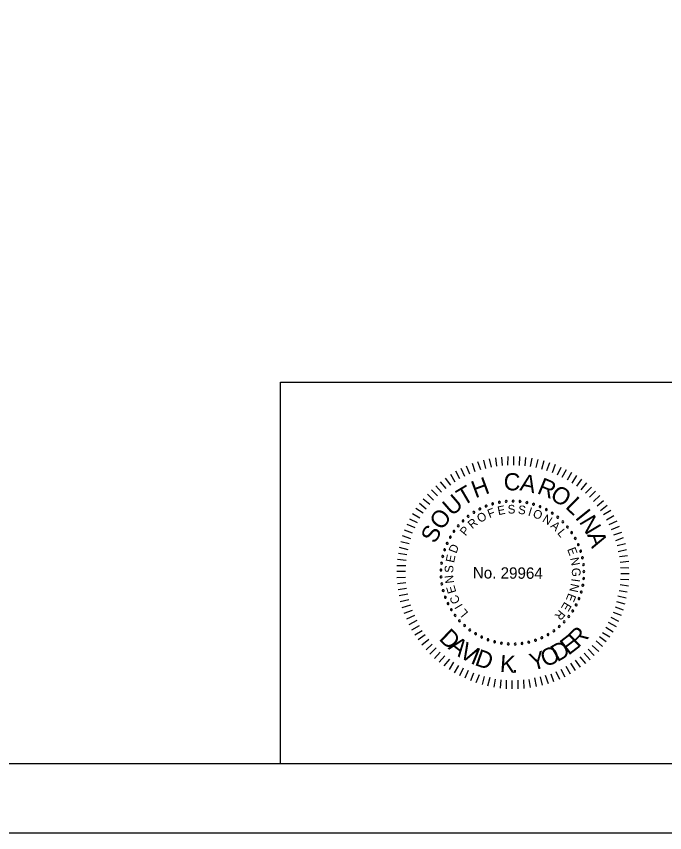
# Model space of a CAD drawing. Extents: x -133.1 to -97, y -1.7 to 20.3.
# Drawn here: x -112.41 to -107.74, y -1.69 to 4.2 of the extents above; entities that cross this region are included whole.
import ezdxf

# ---------------------------------------------------------------- set-up
doc = ezdxf.new("R2010")
doc.units = 0
for name, color, linetype in [('BR_BORDER LINES', 7, 'Continuous'), ('BR_TEXT', 7, 'Continuous'), ('Level 31', 7, 'Continuous')]:
    doc.layers.add(name, color=color, linetype=linetype)

msp = doc.modelspace()

# ---------------------------------------------------------------- linework, layer by layer
at = {"layer": 'BR_BORDER LINES'}
for p, q in [((-110.5071, 1.5591), (-105.1419, 1.5591)), ((-110.5071, -1.191), (-110.5071, 1.5591)), ((-131.3076, -1.191), (-97.6416, -1.191))]:
    msp.add_line(p, q, dxfattribs=at)
at = {"layer": 'BR_TEXT'}
for p, q in [((-108.9849, 0.9447), (-108.999, 1.0041)), ((-108.9454, 0.9521), (-108.9543, 1.0131)), ((-108.9059, 0.9561), (-108.9097, 1.017)), ((-108.8664, 0.9584), (-108.8658, 1.0227)), ((-108.8243, 0.9606), (-108.8238, 1.0224)), ((-108.7823, 0.9577), (-108.78, 1.022)), ((-108.742, 0.9548), (-108.7372, 1.0156)), ((-108.7034, 0.9501), (-108.6926, 1.011)), ((-108.6631, 0.9421), (-108.6489, 1.0012)), ((-109.1406, 0.8954), (-109.1642, 0.9514)), ((-109.1019, 0.9122), (-109.1229, 0.9708)), ((-109.0623, 0.9248), (-109.0842, 0.9824)), ((-109.0262, 0.9348), (-109.0394, 0.9958)), ((-108.622, 0.9314), (-108.606, 0.9922)), ((-108.5852, 0.9208), (-108.5633, 0.9781)), ((-108.5458, 0.9076), (-108.5239, 0.9658)), ((-108.5099, 0.8902), (-108.482, 0.9457)), ((-109.2475, 0.8371), (-109.278, 0.8914)), ((-109.2122, 0.8608), (-109.2426, 0.9151)), ((-109.1777, 0.8785), (-109.2039, 0.9345)), ((-108.474, 0.8727), (-108.4427, 0.9282)), ((-108.4364, 0.8544), (-108.4042, 0.9082)), ((-108.4031, 0.8301), (-108.3692, 0.8839)), ((-109.3123, 0.7904), (-109.3522, 0.8405)), ((-109.2786, 0.8159), (-109.3177, 0.8668)), ((-108.3699, 0.8083), (-108.3334, 0.8587)), ((-108.3375, 0.7824), (-108.2968, 0.8318)), ((-109.3745, 0.7386), (-109.4188, 0.7827)), ((-109.3451, 0.7658), (-109.3868, 0.8107)), ((-108.3059, 0.7572), (-108.2627, 0.8014)), ((-108.2779, 0.7295), (-108.2346, 0.7729)), ((-109.4291, 0.6763), (-109.4786, 0.7154)), ((-109.4039, 0.7079), (-109.4474, 0.7503)), ((-108.2498, 0.6984), (-108.2022, 0.74)), ((-109.4551, 0.6431), (-109.5046, 0.683)), ((-108.2226, 0.6664), (-108.1759, 0.7046)), ((-108.1988, 0.6327), (-108.1496, 0.6718)), ((-109.5012, 0.5774), (-109.5549, 0.6096)), ((-109.4768, 0.6141), (-109.5306, 0.6472)), ((-108.1768, 0.6034), (-108.1242, 0.6355)), ((-108.1548, 0.5663), (-108.1013, 0.5976)), ((-109.5361, 0.5065), (-109.5933, 0.5318)), ((-109.5186, 0.5432), (-109.575, 0.5711)), ((-108.137, 0.5318), (-108.0793, 0.5588)), ((-109.5536, 0.468), (-109.6117, 0.4899)), ((-108.1193, 0.4948), (-108.0624, 0.5192)), ((-108.1025, 0.456), (-108.0456, 0.477)), ((-109.5659, 0.4278), (-109.6275, 0.4506)), ((-108.0891, 0.4156), (-108.0314, 0.4374)), ((-109.5854, 0.3498), (-109.6479, 0.3658)), ((-109.5782, 0.3918), (-109.639, 0.4069)), ((-108.079, 0.3794), (-108.0189, 0.3935)), ((-109.596, 0.3138), (-109.6569, 0.3221)), ((-108.0708, 0.3373), (-108.0106, 0.3522)), ((-108.0625, 0.3012), (-108.0033, 0.3084)), ((-109.6006, 0.2727), (-109.6624, 0.2801)), ((-108.056, 0.26), (-107.995, 0.2663)), ((-109.6056, 0.1921), (-109.6682, 0.1926)), ((-109.6035, 0.2333), (-109.6679, 0.2338)), ((-108.0546, 0.2205), (-107.9945, 0.22)), ((-108.0524, 0.1793), (-107.9915, 0.1788)), ((-109.6042, 0.1492), (-109.6686, 0.148)), ((-108.0553, 0.1364), (-107.9952, 0.1342)), ((-109.602, 0.1105), (-109.6638, 0.1033)), ((-109.598, 0.0693), (-109.659, 0.0604)), ((-108.0574, 0.0978), (-107.9965, 0.0896)), ((-109.5881, 0.0297), (-109.6508, 0.0165)), ((-108.0735, 0.0172), (-108.0135, 0.003)), ((-108.0645, 0.0566), (-108.0054, 0.0467)), ((-109.5815, -0.0124), (-109.6426, -0.0265)), ((-109.5698, -0.0493), (-109.6318, -0.0703)), ((-108.0824, -0.0248), (-108.0224, -0.0398)), ((-109.5582, -0.0881), (-109.6167, -0.1091)), ((-108.107, -0.1001), (-108.0506, -0.122)), ((-108.093, -0.0615), (-108.0357, -0.0835)), ((-109.5413, -0.1251), (-109.599, -0.1521)), ((-109.5244, -0.1613), (-109.5813, -0.1909)), ((-108.1428, -0.1727), (-108.0856, -0.2032)), ((-108.1245, -0.1368), (-108.0681, -0.1647)), ((-109.5076, -0.1984), (-109.5619, -0.2297)), ((-109.4838, -0.2355), (-109.5382, -0.2668)), ((-108.1612, -0.2095), (-108.1082, -0.2417)), ((-109.4626, -0.2648), (-109.5127, -0.3013)), ((-108.2063, -0.2752), (-108.1577, -0.3125)), ((-108.1838, -0.2462), (-108.1317, -0.2784)), ((-109.4372, -0.2985), (-109.4873, -0.3376)), ((-109.4125, -0.3321), (-109.4567, -0.373)), ((-108.2583, -0.3417), (-108.2115, -0.3833)), ((-108.2306, -0.3084), (-108.1846, -0.3483)), ((-109.3836, -0.3582), (-109.4286, -0.4032)), ((-109.3547, -0.3884), (-109.3971, -0.4344)), ((-108.3155, -0.397), (-108.273, -0.4437)), ((-108.2869, -0.3672), (-108.2444, -0.413)), ((-109.3222, -0.4144), (-109.363, -0.4613)), ((-109.289, -0.4404), (-109.3289, -0.4882)), ((-109.2583, -0.4622), (-109.2896, -0.5142)), ((-108.4139, -0.4691), (-108.3808, -0.5217)), ((-108.3802, -0.448), (-108.3446, -0.4963)), ((-108.3474, -0.4225), (-108.3075, -0.47)), ((-109.2233, -0.4847), (-109.2546, -0.5386)), ((-109.1891, -0.5048), (-109.2162, -0.5603)), ((-109.1523, -0.5222), (-109.1769, -0.5778)), ((-108.5216, -0.5274), (-108.4947, -0.5835)), ((-108.4855, -0.5106), (-108.455, -0.5666)), ((-108.4475, -0.4911), (-108.4162, -0.5455)), ((-109.1139, -0.5397), (-109.1358, -0.5962)), ((-109.0745, -0.552), (-109.0973, -0.6102)), ((-109.0386, -0.5644), (-109.0528, -0.6235)), ((-108.9974, -0.5716), (-109.0126, -0.6333)), ((-108.9581, -0.5831), (-108.968, -0.6413)), ((-108.9186, -0.5877), (-108.9234, -0.6494)), ((-108.7161, -0.5851), (-108.7062, -0.6435)), ((-108.6756, -0.5742), (-108.6624, -0.6361)), ((-108.6344, -0.5677), (-108.6194, -0.627)), ((-108.5974, -0.556), (-108.5764, -0.6145)), ((-108.5578, -0.5443), (-108.5368, -0.6011)), ((-108.8792, -0.5906), (-108.8797, -0.6524)), ((-108.8372, -0.5935), (-108.8377, -0.6544)), ((-108.7951, -0.5913), (-108.7939, -0.6531)), ((-108.7547, -0.589), (-108.7509, -0.6509))]:
    msp.add_line(p, q, dxfattribs=at)
for centre, start, end in [((-108.8286, 0.7006), 359.52683, 179.52683), ((-109.0689, 0.644), 27.21914, 207.21914), ((-109.0235, 0.6646), 21.68068, 201.68068), ((-109.0235, 0.6646), 201.68068, 21.68068), ((-108.9763, 0.6806), 16.14222, 196.14222), ((-108.9763, 0.6806), 196.14222, 16.14222), ((-108.9278, 0.692), 10.60376, 190.60376), ((-108.9278, 0.692), 190.60376, 10.60376), ((-108.8784, 0.6987), 5.06529, 185.06529), ((-108.8784, 0.6987), 185.06529, 5.06529), ((-108.8286, 0.7006), 179.52683, 359.52683), ((-108.7789, 0.6977), 173.98837, 353.98837), ((-108.7789, 0.6977), 353.98837, 173.98837), ((-108.7296, 0.69), 168.44991, 348.44991), ((-108.7296, 0.69), 348.44991, 168.44991), ((-108.6814, 0.6776), 162.91145, 342.91145), ((-108.6814, 0.6776), 342.91145, 162.91145), ((-108.6345, 0.6606), 157.37299, 337.37299), ((-108.6345, 0.6606), 337.37299, 157.37299), ((-109.1527, 0.5903), 38.29606, 218.29606), ((-109.1527, 0.5903), 218.29606, 38.29606), ((-109.1121, 0.6192), 32.7576, 212.7576), ((-109.1121, 0.6192), 212.7576, 32.7576), ((-109.0689, 0.644), 207.21914, 27.21914), ((-108.5896, 0.6391), 151.83453, 331.83453), ((-108.5896, 0.6391), 331.83453, 151.83453), ((-108.5469, 0.6134), 146.29606, 326.29606), ((-108.5469, 0.6134), 326.29606, 146.29606), ((-108.5069, 0.5837), 320.7576, 140.7576), ((-109.1903, 0.5577), 43.83453, 223.83453), ((-109.1903, 0.5577), 223.83453, 43.83453), ((-108.5069, 0.5837), 140.7576, 320.7576), ((-108.4699, 0.5503), 135.21914, 315.21914), ((-108.4699, 0.5503), 315.21914, 135.21914), ((-109.2553, 0.4822), 54.91145, 234.91145), ((-109.2553, 0.4822), 234.91145, 54.91145), ((-109.2246, 0.5215), 49.37299, 229.37299), ((-109.2246, 0.5215), 229.37299, 49.37299), ((-108.4363, 0.5134), 129.68068, 309.68068), ((-108.4363, 0.5134), 309.68068, 129.68068), ((-108.4065, 0.4735), 124.14222, 304.14222), ((-108.4065, 0.4735), 304.14222, 124.14222), ((-109.282, 0.4402), 60.44991, 240.44991), ((-109.282, 0.4402), 240.44991, 60.44991), ((-108.3806, 0.4309), 118.60376, 298.60376), ((-108.3806, 0.4309), 298.60376, 118.60376), ((-109.3227, 0.3493), 71.52683, 251.52683), ((-109.3227, 0.3493), 251.52683, 71.52683), ((-109.3045, 0.3957), 65.98837, 245.98837), ((-109.3045, 0.3957), 245.98837, 65.98837), ((-108.359, 0.3861), 113.06529, 293.06529), ((-108.359, 0.3861), 293.06529, 113.06529), ((-109.3363, 0.3014), 77.06529, 257.06529), ((-109.3363, 0.3014), 257.06529, 77.06529), ((-108.3418, 0.3393), 107.52683, 287.52683), ((-108.3418, 0.3393), 287.52683, 107.52683), ((-108.3292, 0.2911), 101.98837, 281.98837), ((-108.3292, 0.2911), 281.98837, 101.98837), ((-109.3452, 0.2524), 82.60376, 262.60376), ((-109.3452, 0.2524), 262.60376, 82.60376), ((-108.3213, 0.2419), 96.44991, 276.44991), ((-108.3213, 0.2419), 276.44991, 96.44991), ((-109.3493, 0.2027), 88.14222, 268.14222), ((-109.3493, 0.2027), 268.14222, 88.14222), ((-108.3182, 0.1921), 90.91145, 270.91145), ((-108.3182, 0.1921), 270.91145, 90.91145), ((-109.3486, 0.1529), 93.68068, 273.68068), ((-109.3486, 0.1529), 273.68068, 93.68068), ((-108.3199, 0.1423), 85.37299, 265.37299), ((-108.3199, 0.1423), 265.37299, 85.37299), ((-109.3431, 0.1033), 99.21914, 279.21914), ((-109.3431, 0.1033), 279.21914, 99.21914), ((-109.3328, 0.0546), 104.7576, 284.7576), ((-109.3328, 0.0546), 284.7576, 104.7576), ((-108.3265, 0.0929), 79.83453, 259.83453), ((-108.3265, 0.0929), 259.83453, 79.83453), ((-109.3179, 0.007), 110.29606, 290.29606), ((-109.3179, 0.007), 290.29606, 110.29606), ((-108.3536, -0.0028), 68.7576, 248.7576), ((-108.3536, -0.0028), 248.7576, 68.7576), ((-108.3377, 0.0444), 74.29606, 254.29606), ((-108.3377, 0.0444), 254.29606, 74.29606), ((-109.2985, -0.0389), 115.83453, 295.83453), ((-109.2985, -0.0389), 295.83453, 115.83453), ((-108.374, -0.0483), 63.21914, 243.21914), ((-108.374, -0.0483), 243.21914, 63.21914), ((-109.2747, -0.0826), 121.37299, 301.37299), ((-109.2747, -0.0826), 301.37299, 121.37299), ((-109.2468, -0.1239), 306.91145, 126.91145), ((-108.3986, -0.0916), 57.68068, 237.68068), ((-108.3986, -0.0916), 237.68068, 57.68068), ((-109.2468, -0.1239), 126.91145, 306.91145), ((-109.2151, -0.1624), 132.44991, 312.44991), ((-109.2151, -0.1624), 312.44991, 132.44991), ((-108.4599, -0.1701), 46.60376, 226.60376), ((-108.4599, -0.1701), 226.60376, 46.60376), ((-108.4273, -0.1323), 52.14222, 232.14222), ((-108.4273, -0.1323), 232.14222, 52.14222), ((-109.1798, -0.1975), 137.98837, 317.98837), ((-109.1798, -0.1975), 317.98837, 137.98837), ((-109.1413, -0.2291), 143.52683, 323.52683), ((-109.1413, -0.2291), 323.52683, 143.52683), ((-108.5351, -0.2353), 35.52683, 215.52683), ((-108.5351, -0.2353), 215.52683, 35.52683), ((-108.4959, -0.2045), 41.06529, 221.06529), ((-108.4959, -0.2045), 221.06529, 41.06529), ((-109.0999, -0.2569), 149.06529, 329.06529), ((-109.0999, -0.2569), 329.06529, 149.06529), ((-109.056, -0.2805), 154.60376, 334.60376), ((-109.056, -0.2805), 334.60376, 154.60376), ((-109.01, -0.2997), 340.14222, 160.14222), ((-108.6214, -0.2849), 24.44991, 204.44991), ((-108.6214, -0.2849), 204.44991, 24.44991), ((-108.577, -0.2622), 29.98837, 209.98837), ((-108.577, -0.2622), 209.98837, 29.98837), ((-109.01, -0.2997), 160.14222, 340.14222), ((-108.9624, -0.3145), 165.68068, 345.68068), ((-108.9624, -0.3145), 345.68068, 165.68068), ((-108.9136, -0.3245), 171.21914, 351.21914), ((-108.9136, -0.3245), 351.21914, 171.21914), ((-108.8641, -0.3299), 356.7576, 176.7576), ((-108.8641, -0.3299), 176.7576, 356.7576), ((-108.8142, -0.3304), 2.29606, 182.29606), ((-108.8142, -0.3304), 182.29606, 2.29606), ((-108.7646, -0.3261), 7.83453, 187.83453), ((-108.7646, -0.3261), 187.83453, 7.83453), ((-108.7156, -0.317), 13.37299, 193.37299), ((-108.7156, -0.317), 193.37299, 13.37299), ((-108.6677, -0.3032), 18.91145, 198.91145), ((-108.6677, -0.3032), 198.91145, 18.91145)]:
    msp.add_arc(centre, 0.00701, start, end, dxfattribs=at)
at = {"layer": 'Level 31'}
msp.add_lwpolyline([(-133.1409, -1.691), (-97.141, -1.691), (-97.141, 20.309), (-133.1409, 20.309)], close=True, dxfattribs=at)

# ---------------------------------------------------------------- texts
at = {"layer": 'BR_TEXT'}
for s, height, rotation, p in [('C', 0.1241, 359.54822, (-108.8971, 0.7782)), ('A', 0.1241, 348.19813, (-108.7857, 0.779)), ('H', 0.1241, 20.36371, (-109.1015, 0.7199)), ('R', 0.1241, 337.43439, (-108.6624, 0.7591)), ('T', 0.1241, 30.49921, (-109.1894, 0.6624)), ('O', 0.1239, 326.58689, (-108.5702, 0.7224)), ('U', 0.1241, 40.80225, (-109.2706, 0.5876)), ('L', 0.1241, 315.94879, (-108.4576, 0.6546)), ('F', 0.0622, 20.61271, (-109.0002, 0.577)), ('E', 0.0622, 11.41035, (-108.9351, 0.5987)), ('S', 0.0622, 2.20798, (-108.8672, 0.6097)), ('S', 0.0622, 352.66081, (-108.796, 0.6095)), ('I', 0.0622, 343.11363, (-108.7257, 0.5975)), ('O', 0.1241, 52.0267, (-109.3451, 0.4837)), ('O', 0.0622, 30.84774, (-109.0676, 0.541)), ('O', 0.0622, 338.43918, (-108.6923, 0.5873)), ('N', 0.0622, 328.20415, (-108.6227, 0.5559)), ('I', 0.1241, 308.66128, (-108.3862, 0.5803)), ('N', 0.1241, 300.70365, (-108.3556, 0.5509)), ('R', 0.0622, 40.39491, (-109.1237, 0.4971)), ('A', 0.0622, 318.65698, (-108.5637, 0.5159)), ('S', 0.1239, 63.25114, (-109.3905, 0.3881)), ('P', 0.0622, 49.94209, (-109.1718, 0.4445)), ('L', 0.0622, 309.45461, (-108.5139, 0.4686)), ('A', 0.1241, 289.47921, (-108.2964, 0.4579)), ('D', 0.0622, 69.03644, (-109.2388, 0.3192)), ('E', 0.0622, 291.049, (-108.44, 0.3533)), ('E', 0.0622, 78.23881, (-109.2553, 0.2526)), ('N', 0.0622, 281.84664, (-108.4179, 0.2882)), ('S', 0.0622, 87.78598, (-109.2611, 0.1815)), ('No. 29964', 0.08175, 359.52683, (-109.1199, 0.1431)), ('G', 0.0622, 272.29946, (-108.4061, 0.2179)), ('N', 0.0622, 97.33316, (-109.2549, 0.1105)), ('I', 0.0622, 262.40836, (-108.4065, 0.1441)), ('E', 0.0622, 106.53552, (-109.2379, 0.044)), ('N', 0.0622, 257.73391, (-108.411, 0.1095)), ('C', 0.0622, 116.42662, (-109.208, -0.0235)), ('E', 0.0622, 248.18673, (-108.4291, 0.0406)), ('I', 0.0622, 121.10107, (-109.1899, -0.0534)), ('E', 0.0622, 238.98437, (-108.457, -0.0222)), ('L', 0.0622, 129.95951, (-109.1493, -0.1056)), ('R', 0.0622, 229.78201, (-108.4947, -0.0797)), ('D', 0.1236, 315.40526, (-109.3698, -0.2962)), ('R', 0.1236, 44.59474, (-108.3589, -0.3617)), ('A', 0.1236, 322.83772, (-109.3032, -0.3618)), ('E', 0.1236, 37.53391, (-108.4295, -0.4156)), ('V', 0.1236, 330.51792, (-109.226, -0.42)), ('O', 0.1236, 22.42125, (-108.5997, -0.4996)), ('D', 0.1236, 30.10145, (-108.5104, -0.4626)), ('I', 0.1236, 338.19813, (-109.1418, -0.4674)), ('D', 0.1236, 340.79949, (-109.1119, -0.4808)), ('K', 0.1236, 356.09796, (-108.9267, -0.5314)), ('Y', 0.1236, 14.86491, (-108.6915, -0.5241)), ('.', 0.1236, 3.15879, (-108.838, -0.5377))]:
    msp.add_text(s, height=height, rotation=rotation, dxfattribs=at).set_placement(p)

doc.saveas('drawing.dxf')
